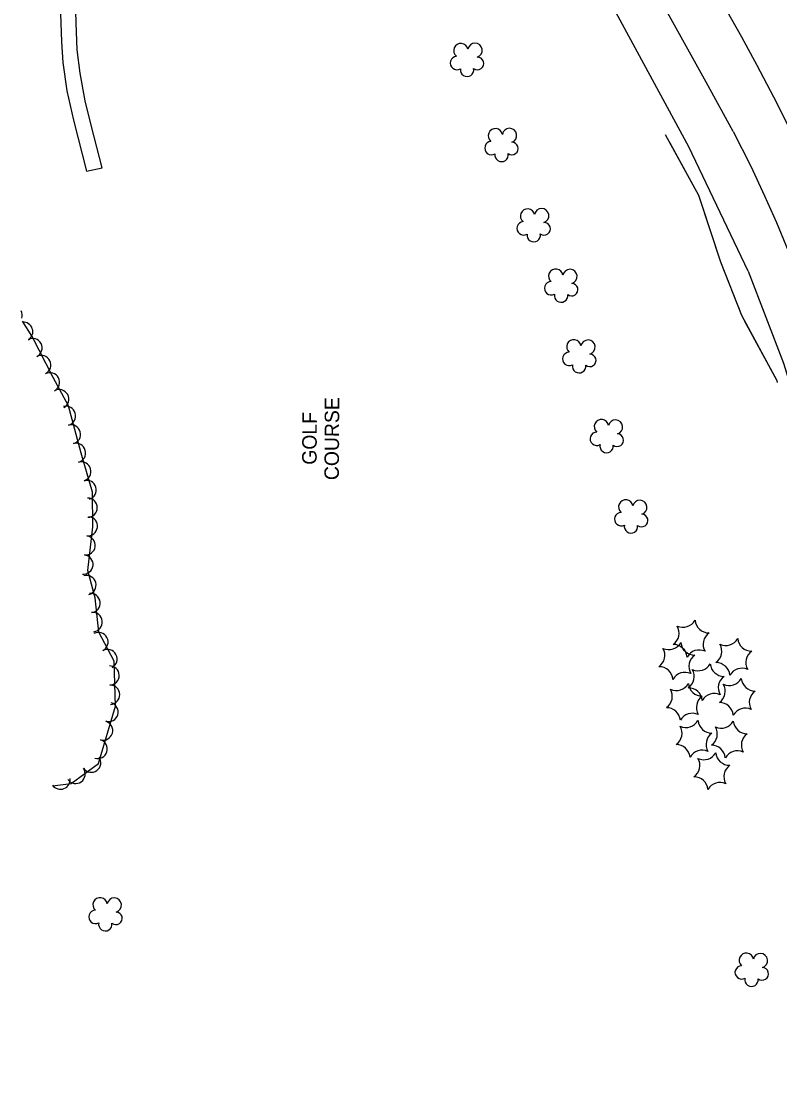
# Model space of a CAD drawing. Extents: x 588843 to 2552415, y 180129 to 269402.
# Drawn here: x 592331.1 to 592645.4, y 185379 to 185814.8 of the extents above; entities that cross this region are included whole.
import ezdxf

# ---------------------------------------------------------------- set-up
doc = ezdxf.new("R2010")
doc.units = 0
for name, color, linetype in [('Level 11', 7, 'Continuous'), ('Level 17', 7, 'Continuous'), ('Level 18', 7, 'Continuous'), ('Level 19', 7, 'Continuous')]:
    doc.layers.add(name, color=color, linetype=linetype)

msp = doc.modelspace()

# ---------------------------------------------------------------- linework, layer by layer
at = {"layer": 'Level 11'}
for points in [[(592626.06, 185768.95), (592614.86, 185789.48), (592600.37, 185815.55), (592586.66, 185839.95), (592572.72, 185864.92), (592560.55, 185886.4), (592547.6, 185909.83), (592541.5, 185921.68), (592536.08, 185934.21), (592532.27, 185945.24), (592528.9, 185958.77), (592526.85, 185971.35), (592525.92, 185985.96), (592525.92, 185995.12)], [(592549.78, 185990.1), (592549.75, 185989.72), (592549.87, 185979.52), (592550.83, 185969.5), (592552.34, 185959.72), (592555.02, 185949.78), (592558.94, 185938.66), (592563.59, 185927.98), (592568.43, 185917.74), (592577.5, 185900.27), (592588.33, 185881.08), (592599.11, 185862.03), (592610.15, 185842.39), (592621.19, 185822.83), (592629.46, 185808.19), (592635.87, 185796.45), (592642.78, 185783.39), (592649.48, 185769.93)], [(592626.06, 185768.95), (592633.33, 185754.6), (592639.04, 185742.33), (592643.96, 185731.23), (592643.96, 185731.35), (592652.7, 185710.16), (592659.12, 185693.13), (592666.78, 185672.46), (592671.64, 185659.23), (592677.66, 185641.32), (592682.83, 185624.55)]]:
    msp.add_lwpolyline(points, dxfattribs=at)
at = {"layer": 'Level 17'}
for points in [[(592632.26, 185711.18), (592607.66, 185762.6), (592570.46, 185831.58), (592529.22, 185903.16), (592512.19, 185932.08), (592503.85, 185952.33), (592503.85, 185986.12), (592512.53, 186000.47)], [(592347.36, 185821.78), (592347.92, 185806.12), (592348.46, 185797.54), (592350.1, 185785.81), (592352.82, 185773.65), (592358.23, 185752.54), (592364.65, 185753.98), (592360.22, 185771.1), (592357.63, 185781.74), (592355.55, 185793.16), (592354.36, 185802.86), (592353.88, 185813.95), (592353.68, 185823.76)], [(592632.26, 185711.18), (592646.89, 185673.04), (592660.35, 185629.45), (592669.4, 185585.85), (592679.43, 185538.57), (592686.09, 185493.67), (592690.29, 185451.79), (592691.76, 185405.78), (592691.87, 185353.19), (592691.53, 185306.74), (592691.13, 185249.27), (592691.18, 185196.22), (592690.64, 185132.51), (592691.01, 185060.47), (592691.33, 184985.54), (592691.73, 184963.57)]]:
    msp.add_lwpolyline(points, dxfattribs=at)
at = {"layer": 'Level 18'}
msp.add_lwpolyline([(592344.16, 185497.93), (592351.82, 185498.96), (592363.22, 185507.13), (592370.25, 185530.95), (592369.72, 185549.63), (592363.35, 185561.55), (592361.76, 185575.79), (592358.76, 185587.08), (592360.83, 185605.24), (592360.76, 185619.53), (592356.06, 185635.77), (592350.78, 185655.34), (592344.42, 185667.11), (592335.74, 185684.12), (592331.67, 185690.38)], dxfattribs=at)
for centre, radius, start, end in [((592513.28, 185802.49), 2.97, 10.7891, 232.023), ((592519.14, 185802.62), 2.97, 288.4399, 171.4132), ((592511.64, 185797.37), 2.78, 93.76, 301.533), ((592520.13, 185797.18), 2.61, 233.1451, 91.0777), ((592515.83, 185794.54), 2.78, 170.437, 11.448), ((592527.57, 185767.23), 2.97, 10.7891, 232.023), ((592533.42, 185767.36), 2.97, 288.4399, 171.4132), ((592525.92, 185762.11), 2.78, 93.76, 301.533), ((592534.41, 185761.93), 2.61, 233.1451, 91.0777), ((592530.12, 185759.28), 2.78, 170.437, 11.448), ((592540.87, 185733.99), 2.97, 10.7891, 232.023), ((592546.72, 185734.12), 2.97, 288.4399, 171.4132), ((592539.22, 185728.88), 2.78, 93.76, 301.533), ((592547.71, 185728.69), 2.61, 233.1451, 91.0777), ((592543.42, 185726.05), 2.78, 170.437, 11.448), ((592552.58, 185709.08), 2.97, 8.1171, 229.351), ((592558.43, 185708.93), 2.97, 285.7679, 168.7412), ((592550.7, 185704.04), 2.78, 91.088, 298.861), ((592559.17, 185703.46), 2.61, 230.4731, 88.4057), ((592554.76, 185701.02), 2.78, 167.765, 8.776), ((592327.66, 185692.73), 3.98, 344.6539, 30.2361), ((592332, 185686.05), 3.98, 302.9988, 94.0307), ((592335.84, 185679.33), 3.98, 297.049, 117.0337), ((592560.06, 185679.8), 2.97, 8.1171, 229.351), ((592565.91, 185679.66), 2.97, 285.7679, 168.7412), ((592339.46, 185672.24), 3.98, 297.049, 117.0337), ((592558.18, 185674.77), 2.78, 91.088, 298.861), ((592566.65, 185674.19), 2.61, 230.4731, 88.4057), ((592562.24, 185671.75), 2.78, 167.765, 8.776), ((592343.13, 185665.11), 3.98, 298.3899, 118.3746), ((592346.92, 185658.1), 3.98, 298.3899, 118.3746), ((592349.73, 185651.23), 3.98, 285.1088, 105.0935), ((592571.46, 185646.73), 2.97, 8.1171, 229.351), ((592577.31, 185646.59), 2.97, 285.7679, 168.7412), ((592351.81, 185643.54), 3.98, 285.1088, 105.0935), ((592569.57, 185641.7), 2.78, 91.088, 298.861), ((592353.88, 185635.85), 3.98, 285.1088, 105.0935), ((592578.04, 185641.11), 2.61, 230.4731, 88.4057), ((592573.63, 185638.68), 2.78, 167.765, 8.776), ((592356.09, 185628.16), 3.98, 286.1513, 106.136), ((592358.31, 185620.51), 3.98, 286.1513, 106.136), ((592358.71, 185613.17), 3.98, 270.2844, 90.2691), ((592581.55, 185613.45), 2.97, 8.1171, 229.351), ((592587.4, 185613.3), 2.97, 285.7679, 168.7412), ((592358.76, 185605.46), 3.98, 263.5128, 83.4974), ((592579.66, 185608.41), 2.78, 91.088, 298.861), ((592588.13, 185607.83), 2.61, 230.4731, 88.4057), ((592583.72, 185605.39), 2.78, 167.765, 8.776), ((592357.86, 185597.54), 3.98, 263.5128, 83.4974), ((592356.96, 185589.63), 3.98, 263.5128, 83.4974), ((592358.2, 185581.1), 3.98, 284.8885, 104.8732), ((592359.9, 185573.65), 3.98, 276.3708, 96.3555), ((592360.79, 185565.73), 3.98, 276.3708, 96.3555), ((592605.29, 185569.32), 5.72, 244.9047, 330.6696), ((592615.99, 185567), 5.72, 184.9047, 270.6697), ((592363.17, 185557.46), 3.98, 298.1081, 118.0927), ((592597.94, 185561.21), 5.72, 304.9047, 30.6696), ((592619.33, 185556.58), 5.72, 124.9047, 210.6697), ((592599.4, 185560.07), 5.72, 244.9047, 330.6696), ((592610.09, 185557.76), 5.72, 184.9047, 270.6697), ((592622.97, 185561.76), 5.72, 244.9047, 330.6696), ((592633.67, 185559.45), 5.72, 184.9047, 270.6697), ((592366.92, 185550.43), 3.98, 298.1081, 118.0927), ((592592.04, 185551.97), 5.72, 304.9047, 30.6696), ((592601.28, 185550.79), 5.72, 4.9047, 90.6696), ((592611.98, 185548.48), 5.72, 64.9047, 150.6696), ((592615.62, 185553.65), 5.72, 304.9047, 30.6696), ((592637.01, 185549.03), 5.72, 124.9047, 210.6697), ((592613.43, 185547.34), 5.72, 124.9047, 210.6697), ((592611.54, 185551.32), 5.72, 244.9047, 330.6696), ((592622.23, 185549.01), 5.72, 184.9047, 270.6697), ((592618.96, 185543.24), 5.72, 4.9047, 90.6696), ((592367.8, 185543.63), 3.98, 271.6484, 91.6331), ((592595.39, 185541.55), 5.72, 4.9047, 90.6696), ((592606.08, 185539.23), 5.72, 64.9047, 150.6696), ((592604.19, 185543.22), 5.72, 304.9047, 30.6696), ((592629.66, 185540.92), 5.72, 64.9047, 150.6696), ((592368.03, 185535.67), 3.98, 271.6484, 91.6331), ((592602.48, 185543.11), 5.72, 244.9047, 330.6696), ((592613.18, 185540.8), 5.72, 184.9047, 270.6697), ((592625.57, 185538.59), 5.72, 124.9047, 210.6697), ((592617.05, 185537.13), 5.72, 304.9047, 30.6696), ((592624.4, 185545.23), 5.72, 244.9047, 330.6696), ((592635.1, 185542.92), 5.72, 184.9047, 270.6697), ((592595.13, 185535.01), 5.72, 304.9047, 30.6696), ((592607.53, 185532.8), 5.72, 4.9047, 90.6696), ((592616.52, 185530.38), 5.72, 124.9047, 210.6697), ((592618.22, 185530.49), 5.72, 64.9047, 150.6696), ((592638.44, 185532.5), 5.72, 124.9047, 210.6697), ((592367.35, 185528.49), 3.98, 253.5692, 73.5538), ((592620.39, 185526.71), 5.72, 4.9047, 90.6696), ((592598.47, 185524.59), 5.72, 4.9047, 90.6696), ((592609.17, 185522.27), 5.72, 64.9047, 150.6696), ((592631.09, 185524.39), 5.72, 64.9047, 150.6696), ((592365.1, 185520.85), 3.98, 253.5692, 73.5538), ((592599.14, 185519.72), 5.72, 304.9047, 30.6696), ((592606.49, 185527.83), 5.72, 244.9047, 330.6696), ((592617.19, 185525.51), 5.72, 184.9047, 270.6697), ((592613.76, 185519.44), 5.72, 304.9047, 30.6696), ((592621.11, 185527.54), 5.72, 244.9047, 330.6696), ((592631.81, 185525.23), 5.72, 184.9047, 270.6697), ((592620.53, 185515.09), 5.72, 124.9047, 210.6697), ((592635.15, 185514.81), 5.72, 124.9047, 210.6697), ((592362.84, 185513.21), 3.98, 253.5692, 73.5538), ((592602.48, 185509.3), 5.72, 4.9047, 90.6696), ((592617.1, 185509.02), 5.72, 4.9047, 90.6696), ((592360.19, 185507.52), 3.98, 215.6327, 35.6174), ((592613.18, 185506.99), 5.72, 64.9047, 150.6696), ((592606.53, 185506.37), 5.72, 304.9047, 30.6696), ((592613.88, 185514.47), 5.72, 244.9047, 330.6696), ((592624.57, 185512.16), 5.72, 184.9047, 270.6697), ((592627.8, 185506.71), 5.72, 64.9047, 150.6696), ((592353.71, 185502.88), 3.98, 215.6327, 35.6174), ((592627.91, 185501.74), 5.72, 124.9047, 210.6697), ((592347.44, 185500.47), 3.98, 214.812, 7.6535), ((592609.87, 185495.95), 5.72, 4.9047, 90.6696), ((592620.56, 185493.64), 5.72, 64.9047, 150.6696), ((592363.85, 185448.66), 2.97, 8.1171, 229.351), ((592369.7, 185448.51), 2.97, 285.7679, 168.7412), ((592361.96, 185443.62), 2.78, 91.088, 298.861), ((592370.43, 185443.04), 2.61, 230.4731, 88.4057), ((592366.02, 185440.6), 2.78, 167.765, 8.776), ((592631.47, 185425.67), 2.97, 8.1171, 229.351), ((592637.32, 185425.53), 2.97, 285.7679, 168.7412), ((592629.58, 185420.64), 2.78, 91.088, 298.861), ((592638.05, 185420.05), 2.61, 230.4731, 88.4057), ((592633.64, 185417.61), 2.78, 167.765, 8.776)]:
    msp.add_arc(centre, radius, start, end, dxfattribs=at)
at = {"layer": 'Level 19'}
for points in [[(592644.44, 185665.01), (592644.21, 185665.77), (592629.59, 185692.8), (592620.98, 185714.81), (592611.79, 185742.47), (592598.03, 185767.58)], [(592613.15, 185738.39), (592611.79, 185742.47), (592599.92, 185764.13)], [(592622.5, 185710.94), (592620.98, 185714.81), (592613.15, 185738.39)], [(592624.68, 185705.36), (592623.95, 185707.22)], [(592626.87, 185699.77), (592626.14, 185701.63)], [(592629.06, 185694.18), (592628.33, 185696.04)], [(592644.44, 185665.01), (592644.21, 185665.77), (592630.79, 185690.58)]]:
    msp.add_lwpolyline(points, dxfattribs=at)

# ---------------------------------------------------------------- texts
at = {"layer": 'Level 17'}
for s, p in [('COURSE', (592462.73, 185624.56)), ('GOLF', (592453.52, 185630.92))]:
    msp.add_text(s, height=6, rotation=89.6934, dxfattribs=at).set_placement(p)

doc.saveas('drawing.dxf')
